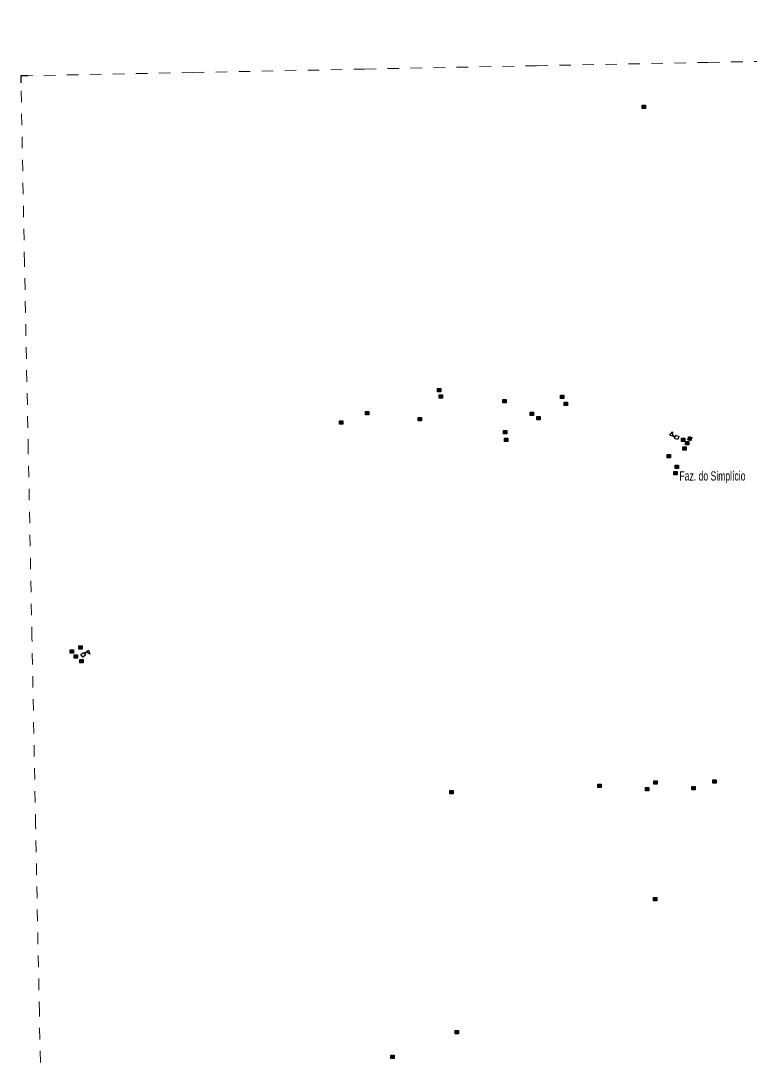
# Model space of a CAD drawing. Extents: x 220.8 to 246.7, y 7287.6 to 7315.8.
# Drawn here: x 220.75 to 227.09, y 7306.72 to 7315.78 of the extents above; entities that cross this region are included whole.
import ezdxf

# ---------------------------------------------------------------- set-up
doc = ezdxf.new("R2010")
doc.units = 0
doc.header["$LTSCALE"] = 0.032
doc.linetypes.add('SHORT_DASHED', pattern=[2.7, 1.5, -1.2])
for name, color, linetype, lineweight in [('2', 7, 'Continuous', 25), ('4', 7, 'Continuous', 25), ('58', 7, 'SHORT_DASHED', 13), ('63', 7, 'Continuous', 25)]:
    doc.layers.add(name, color=color, linetype=linetype, lineweight=lineweight)
doc.layers.add('61', color=7, linetype='Continuous')

msp = doc.modelspace()

# ---------------------------------------------------------------- hatches: boundary and pattern name
at = {"layer": '2'}
for points in [[(226.1555, 7315.0505), (226.1845, 7315.0505), (226.1845, 7315.0215), (226.1555, 7315.0215)], [(224.3751, 7312.5875), (224.4041, 7312.5875), (224.4041, 7312.5585), (224.3751, 7312.5585)], [(224.3912, 7312.5327), (224.4202, 7312.5327), (224.4202, 7312.5037), (224.3912, 7312.5037)], [(225.4466, 7312.529), (225.4756, 7312.529), (225.4756, 7312.5), (225.4466, 7312.5)], [(224.9433, 7312.4922), (224.9723, 7312.4922), (224.9723, 7312.4632), (224.9433, 7312.4632)], [(225.4777, 7312.4696), (225.5067, 7312.4696), (225.5067, 7312.4406), (225.4777, 7312.4406)], [(223.7503, 7312.3878), (223.7793, 7312.3878), (223.7793, 7312.3588), (223.7503, 7312.3588)], [(224.2077, 7312.3362), (224.2367, 7312.3362), (224.2367, 7312.3072), (224.2077, 7312.3072)], [(225.1808, 7312.382), (225.2098, 7312.382), (225.2098, 7312.353), (225.1808, 7312.353)], [(225.2402, 7312.3424), (225.2692, 7312.3424), (225.2692, 7312.3134), (225.2402, 7312.3134)], [(223.5248, 7312.3073), (223.5538, 7312.3073), (223.5538, 7312.2783), (223.5248, 7312.2783)], [(224.949, 7312.2208), (224.978, 7312.2208), (224.978, 7312.1918), (224.949, 7312.1918)], [(224.9603, 7312.1557), (224.9893, 7312.1557), (224.9893, 7312.1267), (224.9603, 7312.1267)], [(226.4974, 7312.1539), (226.5264, 7312.1539), (226.5264, 7312.1249), (226.4974, 7312.1249)], [(226.5612, 7312.169), (226.5887, 7312.1598), (226.5795, 7312.1323), (226.552, 7312.1415)], [(226.509, 7312.0785), (226.538, 7312.0785), (226.538, 7312.0495), (226.509, 7312.0495)], [(226.5322, 7312.1249), (226.5612, 7312.1249), (226.5612, 7312.0959), (226.5322, 7312.0959)], [(226.3727, 7312.0118), (226.4017, 7312.0118), (226.4017, 7311.9828), (226.3727, 7311.9828)], [(226.4423, 7311.9219), (226.4713, 7311.9219), (226.4713, 7311.8929), (226.4423, 7311.8929)], [(226.4307, 7311.8668), (226.4597, 7311.8668), (226.4597, 7311.8378), (226.4307, 7311.8378)], [(221.2588, 7310.3492), (221.2878, 7310.3492), (221.2878, 7310.3202), (221.2588, 7310.3202)], [(221.1836, 7310.3144), (221.2126, 7310.3144), (221.2126, 7310.2854), (221.1836, 7310.2854)], [(221.2185, 7310.2723), (221.2475, 7310.2723), (221.2475, 7310.2433), (221.2185, 7310.2433)], [(221.2661, 7310.2301), (221.2951, 7310.2301), (221.2951, 7310.2011), (221.2661, 7310.2011)], [(226.258, 7309.1749), (226.287, 7309.1749), (226.287, 7309.1459), (226.258, 7309.1459)], [(226.7698, 7309.1857), (226.7988, 7309.1857), (226.7988, 7309.1567), (226.7698, 7309.1567)], [(224.4849, 7309.0913), (224.5139, 7309.0913), (224.5139, 7309.0623), (224.4849, 7309.0623)], [(225.7702, 7309.1478), (225.7992, 7309.1478), (225.7992, 7309.1188), (225.7702, 7309.1188)], [(226.1851, 7309.1186), (226.2141, 7309.1186), (226.2141, 7309.0896), (226.1851, 7309.0896)], [(226.587, 7309.1267), (226.616, 7309.1267), (226.616, 7309.0977), (226.587, 7309.0977)], [(226.2553, 7308.1625), (226.2843, 7308.1625), (226.2843, 7308.1335), (226.2553, 7308.1335)], [(224.5315, 7307.005), (224.5605, 7307.005), (224.5605, 7306.976), (224.5315, 7306.976)], [(223.9697, 7306.7901), (223.9987, 7306.7901), (223.9987, 7306.7611), (223.9697, 7306.7611)]]:
    msp.add_hatch(color=256, dxfattribs=at).paths.add_polyline_path(points)

# ---------------------------------------------------------------- linework, layer by layer
for points in [[(226.1555, 7315.0505), (226.1845, 7315.0505), (226.1845, 7315.0215), (226.1555, 7315.0215)], [(224.3751, 7312.5875), (224.4041, 7312.5875), (224.4041, 7312.5585), (224.3751, 7312.5585)], [(224.3912, 7312.5327), (224.4202, 7312.5327), (224.4202, 7312.5037), (224.3912, 7312.5037)], [(225.4466, 7312.529), (225.4756, 7312.529), (225.4756, 7312.5), (225.4466, 7312.5)], [(224.9433, 7312.4922), (224.9723, 7312.4922), (224.9723, 7312.4632), (224.9433, 7312.4632)], [(225.4777, 7312.4696), (225.5067, 7312.4696), (225.5067, 7312.4406), (225.4777, 7312.4406)], [(223.7503, 7312.3878), (223.7793, 7312.3878), (223.7793, 7312.3588), (223.7503, 7312.3588)], [(224.2077, 7312.3362), (224.2367, 7312.3362), (224.2367, 7312.3072), (224.2077, 7312.3072)], [(225.1808, 7312.382), (225.2098, 7312.382), (225.2098, 7312.353), (225.1808, 7312.353)], [(225.2402, 7312.3424), (225.2692, 7312.3424), (225.2692, 7312.3134), (225.2402, 7312.3134)], [(223.5248, 7312.3073), (223.5538, 7312.3073), (223.5538, 7312.2783), (223.5248, 7312.2783)], [(224.949, 7312.2208), (224.978, 7312.2208), (224.978, 7312.1918), (224.949, 7312.1918)], [(224.9603, 7312.1557), (224.9893, 7312.1557), (224.9893, 7312.1267), (224.9603, 7312.1267)], [(226.4974, 7312.1539), (226.5264, 7312.1539), (226.5264, 7312.1249), (226.4974, 7312.1249)], [(226.5612, 7312.169), (226.5887, 7312.1598), (226.5795, 7312.1323), (226.552, 7312.1415)], [(226.509, 7312.0785), (226.538, 7312.0785), (226.538, 7312.0495), (226.509, 7312.0495)], [(226.5322, 7312.1249), (226.5612, 7312.1249), (226.5612, 7312.0959), (226.5322, 7312.0959)], [(226.3727, 7312.0118), (226.4017, 7312.0118), (226.4017, 7311.9828), (226.3727, 7311.9828)], [(226.4423, 7311.9219), (226.4713, 7311.9219), (226.4713, 7311.8929), (226.4423, 7311.8929)], [(226.4307, 7311.8668), (226.4597, 7311.8668), (226.4597, 7311.8378), (226.4307, 7311.8378)], [(221.2588, 7310.3492), (221.2878, 7310.3492), (221.2878, 7310.3202), (221.2588, 7310.3202)], [(221.1836, 7310.3144), (221.2126, 7310.3144), (221.2126, 7310.2854), (221.1836, 7310.2854)], [(221.2185, 7310.2723), (221.2475, 7310.2723), (221.2475, 7310.2433), (221.2185, 7310.2433)], [(221.2661, 7310.2301), (221.2951, 7310.2301), (221.2951, 7310.2011), (221.2661, 7310.2011)], [(226.258, 7309.1749), (226.287, 7309.1749), (226.287, 7309.1459), (226.258, 7309.1459)], [(226.7698, 7309.1857), (226.7988, 7309.1857), (226.7988, 7309.1567), (226.7698, 7309.1567)], [(224.4849, 7309.0913), (224.5139, 7309.0913), (224.5139, 7309.0623), (224.4849, 7309.0623)], [(225.7702, 7309.1478), (225.7992, 7309.1478), (225.7992, 7309.1188), (225.7702, 7309.1188)], [(226.1851, 7309.1186), (226.2141, 7309.1186), (226.2141, 7309.0896), (226.1851, 7309.0896)], [(226.587, 7309.1267), (226.616, 7309.1267), (226.616, 7309.0977), (226.587, 7309.0977)], [(226.2553, 7308.1625), (226.2843, 7308.1625), (226.2843, 7308.1335), (226.2553, 7308.1335)], [(224.5315, 7307.005), (224.5605, 7307.005), (224.5605, 7306.976), (224.5315, 7306.976)], [(223.9697, 7306.7901), (223.9987, 7306.7901), (223.9987, 7306.7611), (223.9697, 7306.7611)]]:
    msp.add_lwpolyline(points, close=True, dxfattribs=at)
at = {"layer": '4'}
for points in [[(226.4424, 7312.1646), (226.3973, 7312.1821), (226.4203, 7312.2095), (226.4198, 7312.1786), (226.4442, 7312.1692)], [(226.4442, 7312.1692), (226.4485, 7312.1805), (226.4756, 7312.17), (226.4651, 7312.143), (226.4381, 7312.1534), (226.4424, 7312.1646)], [(221.3082, 7310.2791), (221.3155, 7310.2695), (221.2925, 7310.2519), (221.2749, 7310.275), (221.298, 7310.2925), (221.3052, 7310.283)], [(221.3052, 7310.283), (221.3437, 7310.3122), (221.355, 7310.2783), (221.3289, 7310.2949), (221.3082, 7310.2791)]]:
    msp.add_lwpolyline(points, dxfattribs=at)
at = {"layer": '58'}
for points in [[(220.7543, 7315.3049), (222.2482, 7315.3343), (223.7422, 7315.3636), (225.2361, 7315.3926), (226.7301, 7315.4216), (228.224, 7315.4503), (229.718, 7315.4789), (231.2119, 7315.5074), (232.7059, 7315.5357), (234.1998, 7315.5638), (235.6938, 7315.5918), (237.1877, 7315.6196), (238.6817, 7315.6472), (240.1757, 7315.6748), (241.6697, 7315.7021), (243.1636, 7315.7293), (244.6576, 7315.7563), (246.1516, 7315.7832)], [(221.3035, 7287.6034), (221.271, 7289.2329), (221.2386, 7290.8624), (221.2062, 7292.4919), (221.1738, 7294.1214), (221.1414, 7295.7509), (221.109, 7297.3804), (221.0767, 7299.0099), (221.0443, 7300.6394), (221.0121, 7302.2689), (220.9798, 7303.8984), (220.9475, 7305.5279), (220.9153, 7307.1574), (220.883, 7308.7869), (220.8508, 7310.4164), (220.8187, 7312.0459), (220.7865, 7313.6754), (220.7543, 7315.3049)]]:
    msp.add_lwpolyline(points, dxfattribs=at)
at = {"layer": '63'}
msp.add_lwpolyline([(220.8159, 7315.3049), (220.7543, 7315.3049), (220.7543, 7315.2442)], dxfattribs=at)

# ---------------------------------------------------------------- texts
at = {"layer": '61', "width": 0.7}
msp.add_text('Faz. do Simplício', height=0.08, dxfattribs=at).set_placement((226.4796, 7311.787))

doc.saveas('drawing.dxf')
